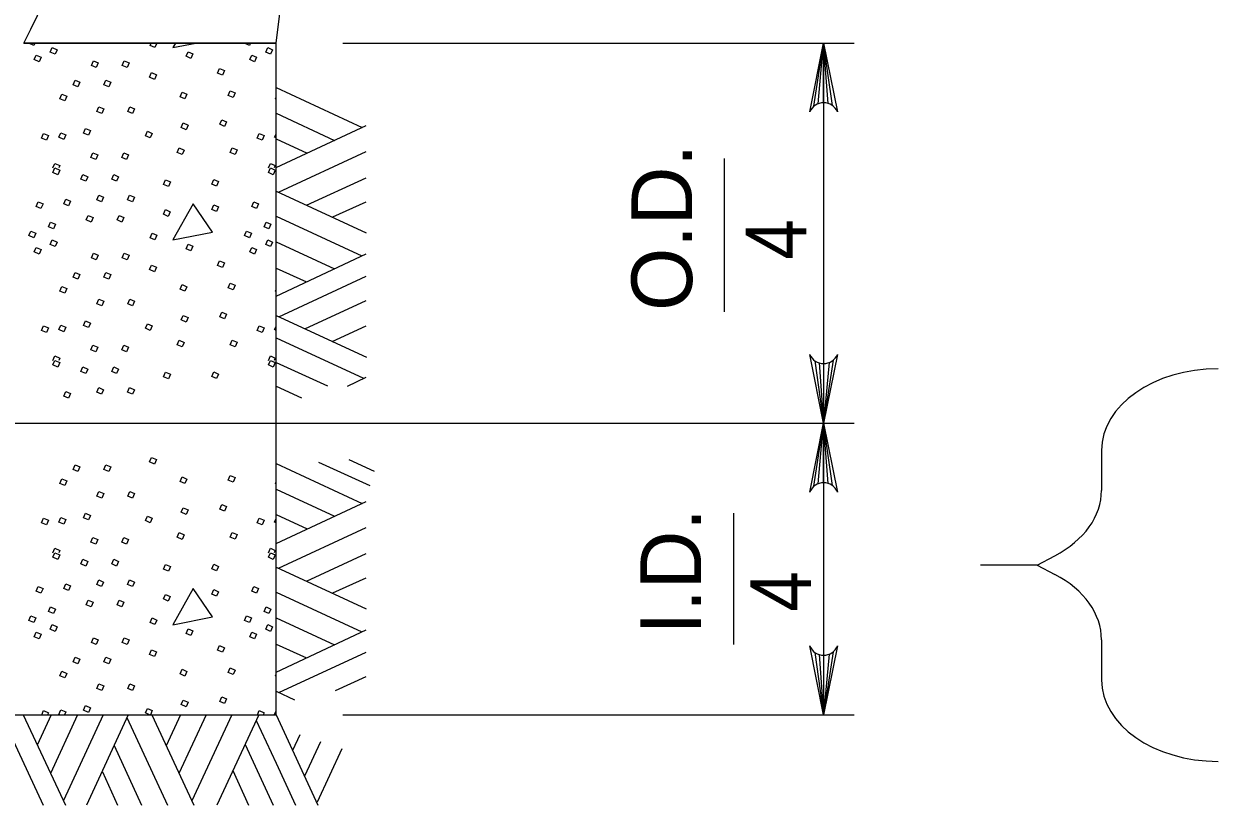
# Model space of a CAD drawing. Extents: x 1083.1 to 1117.1, y 697.4 to 741.4.
# Drawn here: x 1094.266 to 1097.338, y 720.97 to 722.978 of the extents above; entities that cross this region are included whole.
import ezdxf
from ezdxf.enums import TextEntityAlignment as Align

# ---------------------------------------------------------------- set-up
doc = ezdxf.new("R2010")
doc.units = 0
doc.header["$LTSCALE"] = 0.062
doc.layers.add('1', color=7, linetype='Continuous', lineweight=13)

msp = doc.modelspace()

# ---------------------------------------------------------------- linework, layer by layer
at = {"layer": '1', "lineweight": 25}
for p, q in [((1094.915, 722.92817), (1095.17642, 725.01283)), ((1094.26642, 722.92817), (1094.915, 722.92817)), ((1094.26642, 722.92817), (1094.915, 722.92817))]:
    msp.add_line(p, q, dxfattribs=at)
at = {"layer": '1'}
for p, q in [((1094.915, 722.92817), (1094.26642, 722.92817)), ((1095.08633, 722.92817), (1096.40183, 722.92817)), ((1096.29833, 722.76608), (1096.32317, 722.92817)), ((1096.30875, 722.77217), (1096.32317, 722.92817)), ((1096.32317, 722.775), (1096.32317, 722.92817)), ((1096.3345, 722.77333), (1096.32317, 722.92817)), ((1096.34558, 722.76792), (1096.32317, 722.92817)), ((1094.915, 722.81433), (1095.13617, 722.71133)), ((1094.915, 722.74808), (1095.06567, 722.67817)), ((1094.915, 722.60825), (1095.14708, 722.71633)), ((1094.915, 722.68242), (1094.995, 722.64575)), ((1094.9215, 722.54483), (1095.14708, 722.64933)), ((1094.34125, 722.60725), (1094.34625, 722.61867)), ((1094.89558, 722.60725), (1094.90058, 722.61867)), ((1096.06708, 722.63183), (1096.06708, 722.23783)), ((1094.99358, 722.51175), (1095.14708, 722.58225)), ((1094.915, 722.54775), (1095.14708, 722.44033)), ((1095.06133, 722.48142), (1095.14708, 722.52033)), ((1094.915, 722.48358), (1095.1355, 722.38133)), ((1094.915, 722.41725), (1095.06567, 722.34817)), ((1094.915, 722.2775), (1095.14708, 722.38633)), ((1094.915, 722.3495), (1094.99283, 722.31425)), ((1094.92217, 722.22492), (1095.14708, 722.32942)), ((1094.98925, 722.19392), (1095.14708, 722.26667)), ((1094.915, 722.2285), (1095.14783, 722.12117)), ((1095.05917, 722.1615), (1095.14708, 722.20183)), ((1094.915, 722.17083), (1095.13983, 722.06708)), ((1094.34125, 722.11283), (1094.34625, 722.12425)), ((1094.89558, 722.11283), (1094.90058, 722.12425)), ((1094.915, 722.1075), (1095.04683, 722.04733)), ((1096.30075, 722.1115), (1096.32317, 721.95125)), ((1096.31183, 722.10608), (1096.32317, 721.95125)), ((1096.34792, 722.11342), (1096.32317, 721.95125)), ((1096.33758, 722.10725), (1096.32317, 721.95125)), ((1096.32317, 722.10442), (1096.32317, 721.95125)), ((1095.0985, 722.04683), (1095.14708, 722.06925)), ((1094.915, 722.04617), (1094.98, 722.0165)), ((1093.40175, 721.95125), (1096.40183, 721.95125)), ((1096.29833, 721.78908), (1096.32317, 721.95125)), ((1096.30875, 721.79525), (1096.32317, 721.95125)), ((1096.32317, 721.79808), (1096.32317, 721.95125)), ((1096.3345, 721.79642), (1096.32317, 721.95125)), ((1096.34558, 721.791), (1096.32317, 721.95125)), ((1097.03783, 721.88125), (1097.03783, 721.7785)), ((1094.915, 721.848), (1095.13617, 721.745)), ((1095.02442, 721.85092), (1095.15625, 721.79075)), ((1095.102, 721.85808), (1095.16692, 721.82833)), ((1094.915, 721.78175), (1095.06567, 721.71192)), ((1094.915, 721.64192), (1095.14708, 721.75008)), ((1094.915, 721.71617), (1094.995, 721.67942)), ((1096.09108, 721.71983), (1096.09108, 721.38208)), ((1094.9215, 721.57858), (1095.14708, 721.683)), ((1094.34125, 721.61833), (1094.34625, 721.62975)), ((1094.89558, 721.61833), (1094.90058, 721.62975)), ((1094.99358, 721.54542), (1095.14708, 721.61608)), ((1096.87208, 721.5865), (1096.91767, 721.6105)), ((1094.915, 721.5815), (1095.14708, 721.474)), ((1096.87208, 721.5865), (1096.7265, 721.5865)), ((1096.87208, 721.5865), (1096.91767, 721.5625)), ((1095.06133, 721.51508), (1095.14708, 721.55408)), ((1094.915, 721.51733), (1095.1355, 721.415)), ((1094.915, 721.45108), (1095.06567, 721.38175)), ((1094.915, 721.31125), (1095.14708, 721.42008)), ((1097.03783, 721.3945), (1097.03783, 721.29183)), ((1094.915, 721.38325), (1094.99283, 721.348)), ((1094.92217, 721.25867), (1095.14708, 721.36308)), ((1096.30075, 721.36192), (1096.32317, 721.20167)), ((1096.31183, 721.3565), (1096.32317, 721.20167)), ((1096.34792, 721.36383), (1096.32317, 721.20167)), ((1096.33758, 721.35767), (1096.32317, 721.20167)), ((1096.32317, 721.35483), (1096.32317, 721.20167)), ((1095.0675, 721.26375), (1095.14708, 721.30042)), ((1094.915, 721.26225), (1094.96267, 721.24025)), ((1094.26425, 721.20167), (1094.37308, 720.96958)), ((1094.33625, 721.20167), (1094.301, 721.12383)), ((1094.3125, 721.20167), (1094.31725, 721.2125)), ((1094.40408, 721.20167), (1094.33492, 721.05108)), ((1094.47033, 721.20167), (1094.36808, 720.98125)), ((1094.5345, 721.20167), (1094.42717, 720.96958)), ((1094.59508, 721.20167), (1094.70308, 720.96958)), ((1094.66925, 721.20167), (1094.63258, 721.12175)), ((1094.73492, 721.20167), (1094.66492, 721.05108)), ((1094.80117, 721.20167), (1094.69808, 720.9805)), ((1094.87033, 721.20167), (1094.763, 720.96958)), ((1094.86683, 721.20167), (1094.87158, 721.2125)), ((1094.915, 721.20167), (1095.02233, 720.96958)), ((1095.08633, 721.20167), (1096.40183, 721.20167)), ((1094.21167, 721.1945), (1094.31617, 720.96958)), ((1094.53158, 721.19517), (1094.63617, 720.96958)), ((1094.86383, 721.18733), (1094.915, 721.07775)), ((1094.97575, 721.15008), (1094.9575, 721.11017)), ((1094.4985, 721.12317), (1094.56908, 720.96958)), ((1094.83508, 721.12533), (1094.90783, 720.96958)), ((1095.02892, 721.1325), (1094.9885, 721.04392)), ((1095.08375, 721.11442), (1095.02025, 720.97683)), ((1094.46825, 721.05533), (1094.50708, 720.96958)), ((1094.80408, 721.05825), (1094.84433, 720.96958)), ((1094.915, 721.07775), (1094.96467, 720.96958))]:
    msp.add_line(p, q, dxfattribs=at)
at = {"layer": '1', "lineweight": 25}
for points in [[(1091.06575, 722.92817), (1090.41717, 722.92817), (1090.41717, 721.20167), (1094.915, 721.20167), (1094.915, 722.92817)], [(1090.41717, 722.92817), (1090.41717, 721.20167), (1094.915, 721.20167), (1094.915, 722.92817), (1094.26642, 722.92817)]]:
    msp.add_lwpolyline(points, dxfattribs=at)
at = {"layer": '1'}
for points in [[(1094.29442, 722.92817), (1094.29192, 722.92242), (1094.27942, 722.92783), (1094.27958, 722.92817)], [(1094.60842, 722.92817), (1094.60342, 722.91675), (1094.59092, 722.92217), (1094.59358, 722.92817)], [(1094.65608, 722.92817), (1094.64958, 722.91667), (1094.70842, 722.92817)], [(1094.84875, 722.92817), (1094.84625, 722.92242), (1094.83375, 722.92783), (1094.83392, 722.92817)], [(1096.28775, 722.75117), (1096.32317, 722.92817), (1096.35858, 722.75117)], [(1096.32317, 722.92817), (1096.32317, 721.95125), (1096.32317, 721.20167)], [(1094.915, 722.78442), (1094.91317, 722.78525), (1094.915, 722.78958)], [(1094.915, 722.68442), (1094.911, 722.68617), (1094.915, 722.69542)], [(1094.34625, 722.61867), (1094.35875, 722.61325), (1094.35617, 722.60725)], [(1094.90058, 722.61867), (1094.913, 722.61325), (1094.9105, 722.60725)], [(1094.915, 722.29), (1094.91317, 722.29083), (1094.915, 722.29508)], [(1094.915, 722.18992), (1094.911, 722.19167), (1094.915, 722.201)], [(1094.34625, 722.12425), (1094.35875, 722.11883), (1094.35617, 722.11283)], [(1094.90058, 722.12425), (1094.913, 722.11883), (1094.9105, 722.11283)], [(1096.35858, 722.12825), (1096.32317, 721.95125), (1096.28775, 722.12825)], [(1096.28775, 721.77425), (1096.32317, 721.95125), (1096.35858, 721.77425)], [(1094.915, 721.7955), (1094.91317, 721.79633), (1094.915, 721.80067)], [(1094.915, 721.6955), (1094.911, 721.69725), (1094.915, 721.7065)], [(1094.34625, 721.62975), (1094.35875, 721.62433), (1094.35617, 721.61833)], [(1094.90058, 721.62975), (1094.913, 721.62433), (1094.9105, 721.61833)], [(1096.35858, 721.37867), (1096.32317, 721.20167), (1096.28775, 721.37867)], [(1094.915, 721.30108), (1094.91317, 721.30183), (1094.915, 721.30617)], [(1094.31725, 721.2125), (1094.32975, 721.20708), (1094.32733, 721.20167)], [(1094.35908, 721.20167), (1094.35667, 721.20275), (1094.36183, 721.21458)], [(1094.36183, 721.21458), (1094.37433, 721.20917), (1094.371, 721.20167)], [(1094.58958, 721.20167), (1094.57883, 721.20633), (1094.584, 721.21817)], [(1094.584, 721.21817), (1094.5965, 721.21275), (1094.59167, 721.20167)], [(1094.87158, 721.2125), (1094.88408, 721.20708), (1094.88167, 721.20167)], [(1094.91342, 721.20167), (1094.911, 721.20275), (1094.915, 721.212)]]:
    msp.add_lwpolyline(points, dxfattribs=at)
for points in [[(1094.29808, 722.89758), (1094.31058, 722.89217), (1094.30542, 722.88033), (1094.29292, 722.88575)], [(1094.33917, 722.91675), (1094.35167, 722.91133), (1094.3465, 722.8995), (1094.334, 722.90492)], [(1094.68883, 722.90608), (1094.70133, 722.90067), (1094.69617, 722.88883), (1094.68367, 722.89425)], [(1094.85242, 722.89758), (1094.86492, 722.89217), (1094.85975, 722.88033), (1094.84725, 722.88575)], [(1094.8935, 722.91675), (1094.906, 722.91133), (1094.90083, 722.8995), (1094.88833, 722.90492)], [(1094.44533, 722.88275), (1094.45783, 722.87742), (1094.45267, 722.86558), (1094.44017, 722.871)], [(1094.52458, 722.88275), (1094.53708, 722.87742), (1094.53192, 722.86558), (1094.51942, 722.871)], [(1094.7695, 722.863), (1094.782, 722.85758), (1094.77683, 722.84575), (1094.76433, 722.85117)], [(1094.39792, 722.83325), (1094.41042, 722.82783), (1094.40525, 722.816), (1094.39275, 722.82142)], [(1094.47717, 722.83325), (1094.48967, 722.82783), (1094.4845, 722.816), (1094.472, 722.82142)], [(1094.59467, 722.85233), (1094.60717, 722.84692), (1094.602, 722.83508), (1094.5895, 722.8405)], [(1094.67325, 722.80208), (1094.68575, 722.79667), (1094.68058, 722.78483), (1094.66808, 722.79025)], [(1094.79717, 722.80558), (1094.80967, 722.80017), (1094.8045, 722.78833), (1094.792, 722.79375)], [(1094.364, 722.79708), (1094.3765, 722.79167), (1094.37133, 722.77983), (1094.35883, 722.78525)], [(1094.4595, 722.7645), (1094.472, 722.75908), (1094.46683, 722.74725), (1094.45433, 722.75267)], [(1094.53875, 722.7645), (1094.55125, 722.75908), (1094.54608, 722.74725), (1094.53358, 722.75267)], [(1094.42483, 722.70867), (1094.43733, 722.70325), (1094.43217, 722.69142), (1094.41967, 722.69683)], [(1094.67617, 722.723), (1094.68867, 722.71758), (1094.6835, 722.70575), (1094.671, 722.71117)], [(1094.77517, 722.73125), (1094.78767, 722.72592), (1094.7825, 722.71408), (1094.77, 722.7195)], [(1094.31725, 722.69592), (1094.32975, 722.6905), (1094.32458, 722.67867), (1094.31208, 722.68408)], [(1094.36183, 722.698), (1094.37433, 722.69258), (1094.36917, 722.68075), (1094.35667, 722.68617)], [(1094.584, 722.70158), (1094.5965, 722.69617), (1094.59133, 722.68433), (1094.57883, 722.68975)], [(1094.87158, 722.69592), (1094.88408, 722.6905), (1094.87892, 722.67867), (1094.86642, 722.68408)], [(1094.44392, 722.64633), (1094.45642, 722.64092), (1094.45125, 722.62908), (1094.43875, 722.6345)], [(1094.52317, 722.64633), (1094.53567, 722.64092), (1094.5305, 722.62908), (1094.518, 722.6345)], [(1094.66575, 722.65883), (1094.67825, 722.65342), (1094.67308, 722.64158), (1094.66058, 722.647)], [(1094.80208, 722.65908), (1094.81458, 722.65367), (1094.80942, 722.64183), (1094.79692, 722.64725)], [(1094.34625, 722.60725), (1094.35875, 722.60183), (1094.35358, 722.59008), (1094.34108, 722.59542)], [(1094.41842, 722.59033), (1094.43092, 722.58492), (1094.42575, 722.57308), (1094.41325, 722.5785)], [(1094.49767, 722.59033), (1094.51017, 722.58492), (1094.505, 722.57308), (1094.4925, 722.5785)], [(1094.90058, 722.60725), (1094.913, 722.60183), (1094.90792, 722.59008), (1094.89542, 722.59542)], [(1094.63075, 722.57692), (1094.64325, 722.5715), (1094.63808, 722.55967), (1094.62558, 722.56508)], [(1094.75467, 722.57758), (1094.76717, 722.57217), (1094.762, 722.56033), (1094.7495, 722.56575)], [(1094.37392, 722.52733), (1094.38633, 722.52192), (1094.38125, 722.51008), (1094.36875, 722.5155)], [(1094.45883, 722.53725), (1094.47133, 722.53183), (1094.46617, 722.52), (1094.45367, 722.52542)], [(1094.53808, 722.53725), (1094.55058, 722.53183), (1094.54542, 722.52), (1094.53292, 722.52542)], [(1094.30308, 722.52025), (1094.31558, 722.51483), (1094.31042, 722.503), (1094.29792, 722.50842)], [(1094.6305, 722.50017), (1094.643, 722.49475), (1094.63783, 722.48292), (1094.62533, 722.48833)], [(1094.70183, 722.51483), (1094.64958, 722.42225), (1094.75183, 722.44225)], [(1094.75467, 722.51242), (1094.76717, 722.507), (1094.762, 722.49517), (1094.7495, 722.50058)], [(1094.85742, 722.52025), (1094.86992, 722.51483), (1094.86475, 722.503), (1094.85225, 722.50842)], [(1094.33492, 722.46783), (1094.34742, 722.46242), (1094.34225, 722.45058), (1094.32975, 722.456)], [(1094.43192, 722.4855), (1094.44442, 722.48008), (1094.43925, 722.46825), (1094.42675, 722.47367)], [(1094.51117, 722.4855), (1094.52367, 722.48008), (1094.5185, 722.46825), (1094.506, 722.47367)], [(1094.88925, 722.46783), (1094.90175, 722.46242), (1094.89658, 722.45058), (1094.88408, 722.456)], [(1094.28458, 722.44525), (1094.29708, 722.43983), (1094.29192, 722.428), (1094.27942, 722.43342)], [(1094.59608, 722.43958), (1094.60858, 722.43417), (1094.60342, 722.42233), (1094.59092, 722.42775)], [(1094.83892, 722.44525), (1094.85142, 722.43983), (1094.84625, 722.428), (1094.83375, 722.43342)], [(1094.29808, 722.40317), (1094.31058, 722.39775), (1094.30542, 722.38592), (1094.29292, 722.39133)], [(1094.33917, 722.42233), (1094.35167, 722.41692), (1094.3465, 722.40508), (1094.334, 722.4105)], [(1094.68883, 722.41167), (1094.70133, 722.40625), (1094.69617, 722.39442), (1094.68367, 722.39983)], [(1094.85242, 722.40317), (1094.86492, 722.39775), (1094.85975, 722.38592), (1094.84725, 722.39133)], [(1094.8935, 722.42233), (1094.906, 722.41692), (1094.90083, 722.40508), (1094.88833, 722.4105)], [(1094.44533, 722.38833), (1094.45783, 722.38292), (1094.45267, 722.37108), (1094.44017, 722.3765)], [(1094.52458, 722.38833), (1094.53708, 722.38292), (1094.53192, 722.37108), (1094.51942, 722.3765)], [(1094.39792, 722.33875), (1094.41042, 722.33333), (1094.40525, 722.3215), (1094.39275, 722.32692)], [(1094.47717, 722.33875), (1094.48967, 722.33333), (1094.4845, 722.3215), (1094.472, 722.32692)], [(1094.59467, 722.35783), (1094.60717, 722.35242), (1094.602, 722.34058), (1094.5895, 722.346)], [(1094.7695, 722.3685), (1094.782, 722.36308), (1094.77683, 722.35125), (1094.76433, 722.35667)], [(1094.67325, 722.30758), (1094.68575, 722.30217), (1094.68058, 722.29042), (1094.66808, 722.29583)], [(1094.79717, 722.31108), (1094.80967, 722.30567), (1094.8045, 722.29392), (1094.792, 722.29933)], [(1094.364, 722.30267), (1094.3765, 722.29725), (1094.37133, 722.28542), (1094.35883, 722.29083)], [(1094.4595, 722.27008), (1094.472, 722.26467), (1094.46683, 722.25283), (1094.45433, 722.25825)], [(1094.53875, 722.27008), (1094.55125, 722.26467), (1094.54608, 722.25283), (1094.53358, 722.25825)], [(1094.67617, 722.2285), (1094.68867, 722.22308), (1094.6835, 722.21125), (1094.671, 722.21667)], [(1094.77517, 722.23683), (1094.78767, 722.23142), (1094.7825, 722.21958), (1094.77, 722.225)], [(1094.31725, 722.20142), (1094.32975, 722.196), (1094.32458, 722.18417), (1094.31208, 722.18958)], [(1094.36183, 722.2035), (1094.37433, 722.19808), (1094.36917, 722.18625), (1094.35667, 722.19167)], [(1094.42483, 722.21417), (1094.43733, 722.20875), (1094.43217, 722.19692), (1094.41967, 722.20233)], [(1094.584, 722.20708), (1094.5965, 722.20167), (1094.59133, 722.18983), (1094.57883, 722.19525)], [(1094.87158, 722.20142), (1094.88408, 722.196), (1094.87892, 722.18417), (1094.86642, 722.18958)], [(1094.66575, 722.16433), (1094.67825, 722.15892), (1094.67308, 722.14717), (1094.66058, 722.15258)], [(1094.80208, 722.16458), (1094.81458, 722.15917), (1094.80942, 722.14742), (1094.79692, 722.15283)], [(1094.44392, 722.15192), (1094.45642, 722.1465), (1094.45125, 722.13467), (1094.43875, 722.14008)], [(1094.52317, 722.15192), (1094.53567, 722.1465), (1094.5305, 722.13467), (1094.518, 722.14008)], [(1094.34625, 722.11283), (1094.35875, 722.10742), (1094.35358, 722.09558), (1094.34108, 722.101)], [(1094.41842, 722.09583), (1094.43092, 722.09042), (1094.42575, 722.07858), (1094.41325, 722.084)], [(1094.49767, 722.09583), (1094.51017, 722.09042), (1094.505, 722.07858), (1094.4925, 722.084)], [(1094.90058, 722.11283), (1094.913, 722.10742), (1094.90792, 722.09558), (1094.89542, 722.101)], [(1094.63075, 722.08242), (1094.64325, 722.077), (1094.63808, 722.06517), (1094.62558, 722.07058)], [(1094.75467, 722.08308), (1094.76717, 722.07767), (1094.762, 722.06583), (1094.7495, 722.07125)], [(1094.37392, 722.03283), (1094.38633, 722.02742), (1094.38125, 722.01567), (1094.36875, 722.021)], [(1094.45883, 722.04275), (1094.47133, 722.03733), (1094.46617, 722.0255), (1094.45367, 722.03092)], [(1094.53808, 722.04275), (1094.55058, 722.03733), (1094.54542, 722.0255), (1094.53292, 722.03092)], [(1094.59467, 721.86342), (1094.60717, 721.858), (1094.602, 721.84617), (1094.5895, 721.85158)], [(1094.39792, 721.84433), (1094.41042, 721.83892), (1094.40525, 721.82708), (1094.39275, 721.8325)], [(1094.47717, 721.84433), (1094.48967, 721.83892), (1094.4845, 721.82708), (1094.472, 721.8325)], [(1094.79717, 721.81667), (1094.80967, 721.81125), (1094.8045, 721.79942), (1094.792, 721.80483)], [(1094.364, 721.80817), (1094.3765, 721.80275), (1094.37133, 721.79092), (1094.35883, 721.79633)], [(1094.67325, 721.81317), (1094.68575, 721.80775), (1094.68058, 721.79592), (1094.66808, 721.80133)], [(1094.4595, 721.77558), (1094.472, 721.77017), (1094.46683, 721.75833), (1094.45433, 721.76375)], [(1094.53875, 721.77558), (1094.55125, 721.77017), (1094.54608, 721.75833), (1094.53358, 721.76375)], [(1094.67617, 721.734), (1094.68867, 721.72858), (1094.6835, 721.71683), (1094.671, 721.72225)], [(1094.77517, 721.74233), (1094.78767, 721.73692), (1094.7825, 721.72517), (1094.77, 721.7305)], [(1094.31725, 721.707), (1094.32975, 721.70158), (1094.32458, 721.68975), (1094.31208, 721.69517)], [(1094.36183, 721.70908), (1094.37433, 721.70367), (1094.36917, 721.69183), (1094.35667, 721.69725)], [(1094.42483, 721.71975), (1094.43733, 721.71433), (1094.43217, 721.7025), (1094.41967, 721.70792)], [(1094.584, 721.71267), (1094.5965, 721.70725), (1094.59133, 721.69542), (1094.57883, 721.70083)], [(1094.87158, 721.707), (1094.88408, 721.70158), (1094.87892, 721.68975), (1094.86642, 721.69517)], [(1094.66575, 721.66992), (1094.67825, 721.6645), (1094.67308, 721.65267), (1094.66058, 721.65808)], [(1094.80208, 721.67017), (1094.81458, 721.66475), (1094.80942, 721.65292), (1094.79692, 721.65833)], [(1094.44392, 721.65742), (1094.45642, 721.652), (1094.45125, 721.64017), (1094.43875, 721.64558)], [(1094.52317, 721.65742), (1094.53567, 721.652), (1094.5305, 721.64017), (1094.518, 721.64558)], [(1094.34625, 721.61833), (1094.35875, 721.61292), (1094.35358, 721.60108), (1094.34108, 721.6065)], [(1094.41842, 721.60133), (1094.43092, 721.59592), (1094.42575, 721.58417), (1094.41325, 721.5895)], [(1094.49767, 721.60133), (1094.51017, 721.59592), (1094.505, 721.58417), (1094.4925, 721.5895)], [(1094.90058, 721.61833), (1094.913, 721.61292), (1094.90792, 721.60108), (1094.89542, 721.6065)], [(1094.63075, 721.58792), (1094.64325, 721.58258), (1094.63808, 721.57075), (1094.62558, 721.57617)], [(1094.75467, 721.58858), (1094.76717, 721.58325), (1094.762, 721.57142), (1094.7495, 721.57683)], [(1094.45883, 721.54833), (1094.47133, 721.54292), (1094.46617, 721.53108), (1094.45367, 721.5365)], [(1094.53808, 721.54833), (1094.55058, 721.54292), (1094.54542, 721.53108), (1094.53292, 721.5365)], [(1094.30308, 721.53133), (1094.31558, 721.52592), (1094.31042, 721.51408), (1094.29792, 721.5195)], [(1094.37392, 721.53842), (1094.38633, 721.533), (1094.38125, 721.52117), (1094.36875, 721.52658)], [(1094.6305, 721.51125), (1094.643, 721.50583), (1094.63783, 721.494), (1094.62533, 721.49942)], [(1094.70183, 721.52592), (1094.64958, 721.43333), (1094.75183, 721.45325)], [(1094.75467, 721.5235), (1094.76717, 721.51808), (1094.762, 721.50625), (1094.7495, 721.51167)], [(1094.85742, 721.53133), (1094.86992, 721.52592), (1094.86475, 721.51408), (1094.85225, 721.5195)], [(1094.33492, 721.47892), (1094.34742, 721.4735), (1094.34225, 721.46167), (1094.32975, 721.46708)], [(1094.43192, 721.49658), (1094.44442, 721.49117), (1094.43925, 721.47933), (1094.42675, 721.48475)], [(1094.51117, 721.49658), (1094.52367, 721.49117), (1094.5185, 721.47933), (1094.506, 721.48475)], [(1094.88925, 721.47892), (1094.90175, 721.4735), (1094.89658, 721.46167), (1094.88408, 721.46708)], [(1094.28458, 721.45625), (1094.29708, 721.45083), (1094.29192, 721.43908), (1094.27942, 721.44442)], [(1094.59608, 721.45058), (1094.60858, 721.44517), (1094.60342, 721.43342), (1094.59092, 721.43883)], [(1094.83892, 721.45625), (1094.85142, 721.45083), (1094.84625, 721.43908), (1094.83375, 721.44442)], [(1094.33917, 721.43342), (1094.35167, 721.428), (1094.3465, 721.41617), (1094.334, 721.42158)], [(1094.68883, 721.42275), (1094.70133, 721.41733), (1094.69617, 721.4055), (1094.68367, 721.41092)], [(1094.8935, 721.43342), (1094.906, 721.428), (1094.90083, 721.41617), (1094.88833, 721.42158)], [(1094.29808, 721.41425), (1094.31058, 721.40883), (1094.30542, 721.397), (1094.29292, 721.40242)], [(1094.44533, 721.39942), (1094.45783, 721.394), (1094.45267, 721.38217), (1094.44017, 721.38758)], [(1094.52458, 721.39942), (1094.53708, 721.394), (1094.53192, 721.38217), (1094.51942, 721.38758)], [(1094.85242, 721.41425), (1094.86492, 721.40883), (1094.85975, 721.397), (1094.84725, 721.40242)], [(1094.59467, 721.36892), (1094.60717, 721.3635), (1094.602, 721.35167), (1094.5895, 721.35708)], [(1094.7695, 721.37958), (1094.782, 721.37417), (1094.77683, 721.36233), (1094.76433, 721.36775)], [(1094.39792, 721.34983), (1094.41042, 721.34442), (1094.40525, 721.33258), (1094.39275, 721.338)], [(1094.47717, 721.34983), (1094.48967, 721.34442), (1094.4845, 721.33258), (1094.472, 721.338)], [(1094.364, 721.31367), (1094.3765, 721.30825), (1094.37133, 721.2965), (1094.35883, 721.30183)], [(1094.67325, 721.31867), (1094.68575, 721.31325), (1094.68058, 721.30142), (1094.66808, 721.30683)], [(1094.79717, 721.32217), (1094.80967, 721.31675), (1094.8045, 721.30492), (1094.792, 721.31033)], [(1094.4595, 721.28117), (1094.472, 721.27575), (1094.46683, 721.26392), (1094.45433, 721.26933)], [(1094.53875, 721.28117), (1094.55125, 721.27575), (1094.54608, 721.26392), (1094.53358, 721.26933)], [(1094.67617, 721.23958), (1094.68867, 721.23417), (1094.6835, 721.22233), (1094.671, 721.22775)], [(1094.77517, 721.24792), (1094.78767, 721.2425), (1094.7825, 721.23067), (1094.77, 721.23608)], [(1094.42483, 721.22525), (1094.43733, 721.21983), (1094.43217, 721.208), (1094.41967, 721.21342)]]:
    msp.add_lwpolyline(points, close=True, dxfattribs=at)
for centre, start, end in [((1096.32319, 722.7369), 22.08782, 157.91395), ((1096.32311, 722.14255), 202.08782, 337.91395), ((1096.32319, 721.75996), 22.08782, 157.91395), ((1096.32311, 721.39298), 202.08782, 337.91395)]:
    msp.add_arc(centre, 0.0382, start, end, dxfattribs=at)
at = {"layer": '1', "lineweight": 25}
msp.add_ellipse((1092.66607, 723.75022), major_axis=(1.79915, 0), ratio=0.999895, start_param=5.8086305, end_param=9.8993328, dxfattribs=at)
msp.add_ellipse((1092.66607, 723.75022), major_axis=(1.79915, 0), ratio=0.999895, start_param=5.8086305, end_param=9.8993328, dxfattribs=at)
at = {"layer": '1'}
for centre, major_axis, start_param, end_param in [((1097.33771, 721.88123), (-0.29986, 0), 4.712389, 6.2831853), ((1096.73799, 721.77852), (0.29986, 0), 5.3548956, 6.2831853), ((1096.73799, 721.3945), (0.29986, 0), 6.2831853, 7.2111816), ((1097.33771, 721.29182), (-0.29986, 0), 6.2831853, 7.8539816)]:
    msp.add_ellipse(centre, major_axis=major_axis, ratio=0.699926, start_param=start_param, end_param=end_param, dxfattribs=at)

# ---------------------------------------------------------------- texts
for s, p in [('O.D.', (1095.98492, 722.45438)), ('I.D.', (1096.00792, 721.57071))]:
    msp.add_text(s, height=0.156, rotation=90, dxfattribs=at).set_placement(p, align=Align.CENTER)
at = {"layer": '1', "width": 0.9}
for p in [(1096.27883, 722.42346), (1096.29083, 721.51896)]:
    msp.add_text('4', height=0.156, rotation=90, dxfattribs=at).set_placement(p, align=Align.CENTER)

doc.saveas('drawing.dxf')
